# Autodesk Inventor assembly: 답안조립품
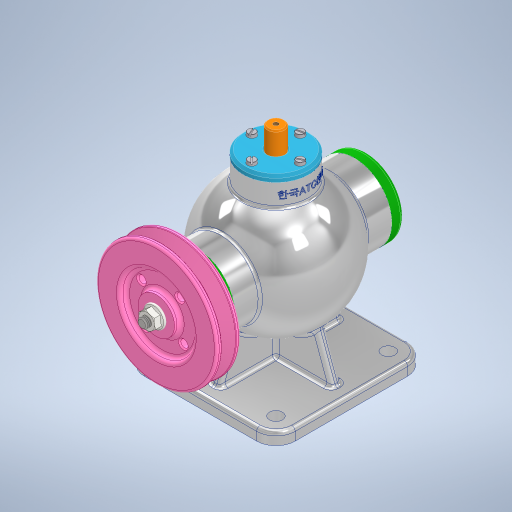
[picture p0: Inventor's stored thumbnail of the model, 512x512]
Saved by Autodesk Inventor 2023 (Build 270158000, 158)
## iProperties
Created: 2023-07
Part Number: 답안조립품
Document SubType Name: Assembly
Designer: Owner
Author: Owner
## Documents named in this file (16)
- C:\Users\Owner\Desktop\730711V1005\답안조립품.iam
- C:\Users\Owner\Desktop\730711V1005\본체.ipt
- C:\Users\Owner\Desktop\730711V1005\뒤커버.ipt
- C:\Users\Owner\Desktop\730711V1005\앞커버.ipt
- C:\Users\Owner\Desktop\730711V1005\상부커버.ipt
- C:\Users\Owner\Desktop\730711V1005\베어링- 6202.ipt
- KS B 2023 - 6202 - 15 x 35 x 11 - 7.8.ipt
- C:\Users\Owner\Desktop\730711V1005\칼라.ipt
- C:\Users\Owner\Desktop\730711V1005\편심축.ipt
- C:\Users\Owner\Desktop\730711V1005\키 4 x 4 x 12.ipt
- C:\Users\Owner\Desktop\730711V1005\오일실 15 30 7.ipt
- C:\Users\Owner\Desktop\730711V1005\V-벨트풀리.ipt
- C:\Users\Owner\Desktop\730711V1005\볼트 M4 x 16.ipt
- C:\Users\Owner\Desktop\730711V1005\볼트 M4 x 12.ipt
- C:\Users\Owner\Desktop\730711V1005\슬라이드.ipt
- C:\Users\Owner\Desktop\730711V1005\너트 M8.ipt
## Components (15 placed, 4 different names)
1. KS B 2023 - 6202 - 15 x 35 x 11 - 7.8:1
2. KS B 2023 - 6202 - 15 x 35 x 11 - 7.8:2
3. V-벨트풀리:1
4. ISO 4762 M4 x 16:1
5. ISO 4762 M4 x 16:2
6. KS B 1021 - 에 따름 ISO 1207 - 미터 A  M 4 x 12:2
7. ISO 4762 M4 x 16:3
8. ISO 4762 M4 x 16:4
9. ISO 4762 M4 x 16:5
10. ISO 4762 M4 x 16:6
11. ISO 4762 M4 x 16:7
12. ISO 4762 M4 x 16:8
13. KS B 1021 - 에 따름 ISO 1207 - 미터 A  M 4 x 12:3
14. KS B 1021 - 에 따름 ISO 1207 - 미터 A  M 4 x 12:4
15. KS B 1021 - 에 따름 ISO 1207 - 미터 A  M 4 x 12:5
